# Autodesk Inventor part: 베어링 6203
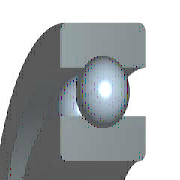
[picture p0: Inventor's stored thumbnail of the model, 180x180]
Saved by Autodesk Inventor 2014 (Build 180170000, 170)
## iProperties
IsCustomPart: 1
Created: 2015-09
Part Number: 베어링 6203
Material: 강철, 연강
Description: 깊은 그루브 볼 베어링
Document SubType Name: Modeling
Standard: KS B 2023
Standards Organization: KS
Language: ko-KR
Size Designation: 6203 - 17 x 40 x 12
Categories: <MemberInstance><Categories><Category DisplayName="샤프트 부품" InternalName="7f7aeb1f-a693-4053-b835-cee3144e0d98" Mnemonic="SHFT"><Category DisplayName="베어링" Inter
Density: 7.86 g/cm^3
Mass: 64.9809 g
Surface Area: 64.3582 cm^2
Volume: 8.26729 cm^3
Appearance: 강철
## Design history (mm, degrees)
sketch "스케치" dims "d0" = 5.98 (= -0.26 x WD + 0.26 x BD)
  geometry: L1 (3.01, 14.25)-(8.99, 14.25); L2 (6, 14.25)-(6, 11.26); L3 (6, 14.25)-(6, 17.24); L4 (3.778, 12.249)-(0, 12.249); L5 (0, 8.5)-(12, 8.5); L6 (3.778, 16.251)-(0, 16.251); L7 (0, 20)-(12, 20); L8 (12, 8.5)-(12, 12.249); L9 (8.222, 12.249)-(12, 12.249); L10 (8.222, 16.251)-(12, 16.251); L11 (12, 20)-(12, 16.251); L12 (-1.4, 0)-(8.4, 0) reference; L13 (0, -0.3)-(0, 5.3) reference
  constraints: 22 end point, 4 point on line, 2 collinear, 2 perpendicular, 2 symmetric about line, 1 midpoint, 1 parallel, 14 other
  dimensions: "d9" = 17 diameter of L5 L12 (= WD); "d11" = 40 diameter of L7 L12 (= BD); "d12" = 12 distance between parallel lines of L8 L13 (= KB); "d13" = 24.498 diameter of L9 L12 (= 0.326 x BD + 0.674 x WD)
revolve "본체" stored, may be unused: angle "d6" = 90 deg
revolve "볼" stored, may be unused: angle "d7" = 90 deg
pattern_circular "IDS_ARRAYBALL[SIMPL:T]" dims angle "d3" = 360 deg
body "Solid1"
fillet "모깎기1" dims "d1" = 0.6 (= KRS)
other parameters: "WD" = 17 [user parameter; used in 5 equation terms], "BD" = 40 [user parameter; used in 5 equation terms], "KB" = 12 [user parameter; used in 1 equation term], "KRS" = 0.6 [user parameter; used in 1 equation term], "d4" = 0, "d5" = 0, "d8" = 0, "d14" = 0, "d15" = 0, "BBA" = 0 [user parameter], "BC0" = 4750000 [user parameter], "BC" = 9560000 [user parameter], "WR" = 8.5 (= 0.5 x WD) [user parameter]
